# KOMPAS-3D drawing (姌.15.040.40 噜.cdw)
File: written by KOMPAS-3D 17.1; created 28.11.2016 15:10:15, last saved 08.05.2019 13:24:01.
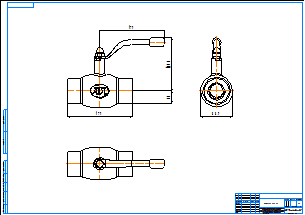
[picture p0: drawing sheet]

Sheet 1: A1, landscape

Title block, sheet 1: name: КШ.15.040.40 рр; material: Внимание! Данный продукт является объектом авторского права ООО «Торговый Дом АДЛ». / Запрещается изменение, копирование, распространение / (в том числе путем копирования на другие сайты и ресурсы в Интернете) / или любое иное использование информации и объектов без предварительного / согласия правообладателя (ООО «Торговый Дом АДЛ»).; sheets: 1; organisation: ООО "Торговый дом АДЛ"; sheet format: A1; stored path: C:\Users\tra\Desktop\2д чертежи\Шаровые краны БИВАЛ\КШ_Бивал_серия_14_15\KOMPAS_2D\КШ.15.040.40 рр.cdw

Views: Вид 1, Проекционный вид 2, Проекционный вид 3
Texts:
  Klimkovich
  ADL
Dimensions and other numbers on the sheet: 179; 147,8; 35; 88,9; 1:1; 1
